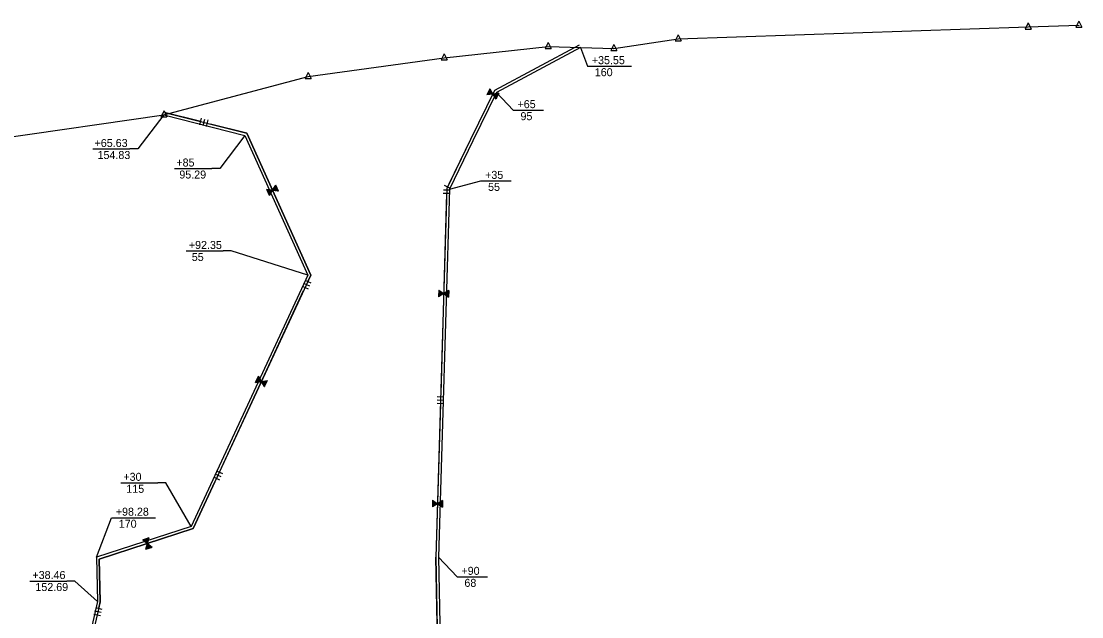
# Model space of a CAD drawing. Extents: x 979729 to 993523, y 1834148 to 1845433.
# Drawn here: x 982395 to 983190, y 1842205 to 1842651 of the extents above; entities that cross this region are included whole.
import ezdxf

# ---------------------------------------------------------------- set-up
doc = ezdxf.new("R2010")
doc.units = 0
for name, color, linetype in [('42', 7, 'Continuous'), ('51', 7, 'Continuous'), ('R_Draft', 7, 'Continuous'), ('S_EXIST_ROW', 7, 'Continuous')]:
    doc.layers.add(name, color=color, linetype=linetype)

msp = doc.modelspace()

# ---------------------------------------------------------------- linework, layer by layer
at = {"layer": '42'}
for p, q in [((982813.71, 1842632.81), (982750.2, 1842598.89)), ((982750.2, 1842598.89), (982732.24, 1842562.08)), ((982747.45, 1842598.61), (982745.78, 1842598.39)), ((982747.34, 1842598.85), (982745.91, 1842598.65)), ((982747.18, 1842599.08), (982746.04, 1842598.93)), ((982747.02, 1842599.31), (982746.18, 1842599.19)), ((982746.91, 1842599.55), (982746.31, 1842599.47)), ((982746.75, 1842599.78), (982746.44, 1842599.73)), ((982746.64, 1842600.01), (982746.57, 1842600.01)), ((982746.61, 1842600.09), (982748.89, 1842596.2)), ((982748.89, 1842596.2), (982744.42, 1842595.6)), ((982748.82, 1842596.27), (982744.46, 1842595.69)), ((982748.63, 1842596.5), (982744.59, 1842595.95)), ((982748.55, 1842596.74), (982744.73, 1842596.23)), ((982748.39, 1842596.97), (982744.86, 1842596.5)), ((982748.27, 1842597.21), (982744.99, 1842596.76)), ((982748.09, 1842597.43), (982745.12, 1842597.03)), ((982748, 1842597.68), (982745.25, 1842597.3)), ((982747.82, 1842597.9), (982745.38, 1842597.57)), ((982747.7, 1842598.14), (982745.52, 1842597.84)), ((982747.51, 1842598.37), (982745.81, 1842598.14)), ((982753.35, 1842596.8), (982748.89, 1842596.2)), ((982748.89, 1842596.2), (982751.16, 1842592.31)), ((982748.99, 1842596.19), (982751.2, 1842592.4)), ((982749.28, 1842596.19), (982751.33, 1842592.67)), ((982749.52, 1842596.26), (982751.47, 1842592.94)), ((982749.8, 1842596.28), (982751.6, 1842593.21)), ((982750.06, 1842596.34), (982751.73, 1842593.48)), ((982750.35, 1842596.33), (982751.86, 1842593.75)), ((982750.6, 1842596.41), (982751.99, 1842594.02)), ((982750.89, 1842596.4), (982752.12, 1842594.29)), ((982751.15, 1842596.46), (982752.26, 1842594.56)), ((982751.44, 1842596.45), (982752.31, 1842594.97)), ((982751.67, 1842596.55), (982752.52, 1842595.1)), ((982751.93, 1842596.61), (982752.65, 1842595.37)), ((982752.2, 1842596.63), (982752.78, 1842595.64)), ((982752.48, 1842596.65), (982752.92, 1842595.91)), ((982752.74, 1842596.7), (982753.05, 1842596.18)), ((982753.02, 1842596.72), (982753.18, 1842596.45)), ((982753.28, 1842596.77), (982753.31, 1842596.72)), ((982502.95, 1842582.46), (982564.55, 1842566.77)), ((982529.41, 1842573.14), (982530.65, 1842577.99)), ((982531.84, 1842572.53), (982533.07, 1842577.37)), ((982534.26, 1842571.91), (982535.49, 1842576.75)), ((982564.55, 1842566.77), (982612.53, 1842460.57)), ((982732.24, 1842562.08), (982714.37, 1842525.46)), ((982583.85, 1842524.05), (982586.24, 1842527.88)), ((982583.95, 1842524.06), (982586.28, 1842527.79)), ((982584.24, 1842524.05), (982586.4, 1842527.51)), ((982584.48, 1842523.97), (982586.53, 1842527.24)), ((982717.15, 1842525.45), (982712.65, 1842527.64)), ((982583.85, 1842524.05), (982579.4, 1842524.79)), ((982583.78, 1842523.98), (982579.44, 1842524.7)), ((982583.59, 1842523.76), (982579.57, 1842524.42)), ((982583.49, 1842523.52), (982579.69, 1842524.15)), ((982583.33, 1842523.3), (982579.81, 1842523.88)), ((982583.21, 1842523.06), (982579.94, 1842523.6)), ((982583.02, 1842522.84), (982580.06, 1842523.33)), ((982582.92, 1842522.6), (982580.19, 1842523.06)), ((982582.73, 1842522.38), (982580.31, 1842522.78)), ((982582.61, 1842522.15), (982580.43, 1842522.51)), ((982582.35, 1842521.69), (982580.68, 1842521.96)), ((982582.41, 1842521.93), (982580.72, 1842522.21)), ((982582.22, 1842521.45), (982580.8, 1842521.69)), ((982582.06, 1842521.23), (982580.93, 1842521.41)), ((982581.9, 1842521), (982581.05, 1842521.14)), ((982581.77, 1842520.77), (982581.17, 1842520.87)), ((982581.61, 1842520.54), (982581.3, 1842520.59)), ((982581.49, 1842520.31), (982581.42, 1842520.32)), ((982581.46, 1842520.23), (982583.85, 1842524.05)), ((982588.3, 1842523.32), (982583.85, 1842524.05)), ((982584.76, 1842523.94), (982586.65, 1842526.96)), ((982585.02, 1842523.88), (982586.77, 1842526.69)), ((982585.31, 1842523.88), (982586.9, 1842526.42)), ((982585.55, 1842523.79), (982587.02, 1842526.14)), ((982585.84, 1842523.79), (982587.14, 1842525.87)), ((982586.1, 1842523.73), (982587.27, 1842525.6)), ((982586.4, 1842523.73), (982587.3, 1842525.18)), ((982586.62, 1842523.62), (982587.52, 1842525.05)), ((982586.88, 1842523.55), (982587.64, 1842524.77)), ((982587.15, 1842523.53), (982587.76, 1842524.5)), ((982587.43, 1842523.5), (982587.89, 1842524.23)), ((982587.69, 1842523.44), (982588.01, 1842523.95)), ((982587.97, 1842523.41), (982588.13, 1842523.68)), ((982588.22, 1842523.35), (982588.26, 1842523.4)), ((982714.37, 1842525.46), (982706.26, 1842249.15)), ((982716.76, 1842521.6), (982711.76, 1842521.74)), ((982716.83, 1842524.1), (982711.83, 1842524.24)), ((982612.53, 1842460.57), (982524.29, 1842270.61)), ((982608.01, 1842456.78), (982612.55, 1842454.67)), ((982605.9, 1842452.25), (982610.44, 1842450.14)), ((982606.96, 1842454.51), (982611.49, 1842452.41)), ((982710.64, 1842447.69), (982708.29, 1842446.22)), ((982710.38, 1842447.82), (982708.3, 1842446.52)), ((982710.18, 1842447.98), (982708.31, 1842446.82)), ((982709.55, 1842448.48), (982708.33, 1842447.72)), ((982709.76, 1842448.31), (982708.33, 1842447.42)), ((982709.32, 1842448.63), (982708.34, 1842448.02)), ((982709.08, 1842448.77), (982708.35, 1842448.32)), ((982708.88, 1842448.94), (982708.36, 1842448.62)), ((982708.64, 1842449.09), (982708.37, 1842448.92)), ((982708.38, 1842449.31), (982712.06, 1842446.7)), ((982708.44, 1842449.25), (982708.38, 1842449.22)), ((982709.91, 1842448.11), (982708.46, 1842447.21)), ((982715.88, 1842449.09), (982712.06, 1842446.7)), ((982713.53, 1842447.6), (982715.79, 1842446)), ((982713.8, 1842447.72), (982715.8, 1842446.3)), ((982714.01, 1842447.87), (982715.81, 1842446.6)), ((982714.29, 1842447.98), (982715.68, 1842446.99)), ((982714.45, 1842448.17), (982715.82, 1842447.2)), ((982714.66, 1842448.33), (982715.83, 1842447.5)), ((982714.9, 1842448.46), (982715.84, 1842447.8)), ((982715.15, 1842448.59), (982715.85, 1842448.1)), ((982715.36, 1842448.75), (982715.86, 1842448.4)), ((982715.61, 1842448.88), (982715.87, 1842448.7)), ((982715.82, 1842449.04), (982715.88, 1842449)), ((982712.06, 1842446.7), (982708.23, 1842444.31)), ((982711.97, 1842446.74), (982708.24, 1842444.41)), ((982711.7, 1842446.88), (982708.25, 1842444.71)), ((982711.29, 1842447.2), (982708.26, 1842445.32)), ((982711.52, 1842447.06), (982708.26, 1842445.02)), ((982711.08, 1842447.37), (982708.27, 1842445.61)), ((982710.82, 1842447.5), (982708.28, 1842445.91)), ((982712.06, 1842446.7), (982715.73, 1842444.09)), ((982712.15, 1842446.74), (982715.73, 1842444.19)), ((982712.42, 1842446.85), (982715.74, 1842444.49)), ((982712.61, 1842447.03), (982715.75, 1842444.79)), ((982712.86, 1842447.16), (982715.76, 1842445.09)), ((982713.07, 1842447.31), (982715.77, 1842445.39)), ((982713.34, 1842447.43), (982715.78, 1842445.69)), ((982574.89, 1842380.83), (982572.88, 1842384.12)), ((982575.13, 1842380.91), (982573.01, 1842384.39)), ((982575.42, 1842380.91), (982573.13, 1842384.66)), ((982575.52, 1842380.9), (982573.18, 1842384.75)), ((982571.07, 1842380.22), (982575.52, 1842380.9)), ((982571.14, 1842380.25), (982571.11, 1842380.3)), ((982571.4, 1842380.31), (982571.24, 1842380.57)), ((982571.68, 1842380.33), (982571.36, 1842380.85)), ((982571.94, 1842380.39), (982571.49, 1842381.12)), ((982572.21, 1842380.41), (982571.62, 1842381.39)), ((982572.49, 1842380.44), (982571.74, 1842381.66)), ((982572.75, 1842380.49), (982571.87, 1842381.94)), ((982572.97, 1842380.61), (982572.08, 1842382.07)), ((982573.27, 1842380.6), (982572.12, 1842382.48)), ((982573.53, 1842380.66), (982572.25, 1842382.75)), ((982573.82, 1842380.66), (982572.38, 1842383.03)), ((982574.06, 1842380.74), (982572.5, 1842383.3)), ((982574.35, 1842380.74), (982572.63, 1842383.57)), ((982574.61, 1842380.8), (982572.75, 1842383.84)), ((982575.52, 1842380.9), (982579.98, 1842381.59)), ((982577.87, 1842377.06), (982575.52, 1842380.9)), ((982575.59, 1842380.83), (982579.94, 1842381.5)), ((982575.78, 1842380.61), (982579.81, 1842381.23)), ((982575.87, 1842380.37), (982579.68, 1842380.96)), ((982576.04, 1842380.14), (982579.56, 1842380.68)), ((982576.16, 1842379.91), (982579.43, 1842380.41)), ((982576.34, 1842379.68), (982579.3, 1842380.14)), ((982576.44, 1842379.44), (982579.18, 1842379.87)), ((982576.63, 1842379.22), (982579.05, 1842379.6)), ((982576.75, 1842378.99), (982578.92, 1842379.32)), ((982576.94, 1842378.76), (982578.63, 1842379.02)), ((982577, 1842378.52), (982578.67, 1842378.78)), ((982577.12, 1842378.29), (982578.54, 1842378.51)), ((982577.28, 1842378.06), (982578.42, 1842378.23)), ((982577.44, 1842377.83), (982578.29, 1842377.96)), ((982577.56, 1842377.59), (982578.16, 1842377.69)), ((982577.73, 1842377.37), (982578.04, 1842377.41)), ((982577.85, 1842377.13), (982577.91, 1842377.14)), ((982712.28, 1842369.16), (982707.28, 1842369.31)), ((982712.13, 1842364.17), (982707.14, 1842364.31)), ((982712.21, 1842366.66), (982707.21, 1842366.81)), ((982541.66, 1842313.94), (982546.2, 1842311.83)), ((982539.56, 1842309.4), (982544.09, 1842307.3)), ((982540.61, 1842311.67), (982545.14, 1842309.56)), ((982707.34, 1842289.31), (982703.61, 1842286.98)), ((982707.43, 1842289.27), (982703.61, 1842286.88)), ((982707.08, 1842289.44), (982703.62, 1842287.28)), ((982706.9, 1842289.63), (982703.63, 1842287.58)), ((982706.66, 1842289.77), (982703.64, 1842287.88)), ((982706.46, 1842289.94), (982703.65, 1842288.18)), ((982706.2, 1842290.07), (982703.66, 1842288.48)), ((982706.02, 1842290.25), (982703.67, 1842288.78)), ((982705.76, 1842290.38), (982703.68, 1842289.08)), ((982705.55, 1842290.55), (982703.69, 1842289.38)), ((982705.14, 1842290.88), (982703.7, 1842289.98)), ((982704.93, 1842291.05), (982703.71, 1842290.28)), ((982704.69, 1842291.19), (982703.72, 1842290.59)), ((982704.46, 1842291.34), (982703.73, 1842290.89)), ((982704.25, 1842291.51), (982703.74, 1842291.19)), ((982704.01, 1842291.65), (982703.75, 1842291.49)), ((982703.76, 1842291.88), (982707.43, 1842289.27)), ((982703.81, 1842291.82), (982703.76, 1842291.79)), ((982705.28, 1842290.68), (982703.84, 1842289.77)), ((982711.26, 1842291.66), (982707.43, 1842289.27)), ((982707.43, 1842289.27), (982711.11, 1842286.66)), ((982707.53, 1842289.31), (982711.11, 1842286.76)), ((982707.8, 1842289.42), (982711.12, 1842287.06)), ((982707.99, 1842289.59), (982711.13, 1842287.36)), ((982708.23, 1842289.73), (982711.14, 1842287.66)), ((982708.44, 1842289.88), (982711.15, 1842287.96)), ((982708.71, 1842290), (982711.16, 1842288.26)), ((982708.9, 1842290.17), (982711.16, 1842288.56)), ((982709.17, 1842290.28), (982711.17, 1842288.86)), ((982709.39, 1842290.44), (982711.18, 1842289.16)), ((982709.66, 1842290.55), (982711.06, 1842289.56)), ((982709.82, 1842290.74), (982711.2, 1842289.76)), ((982710.04, 1842290.9), (982711.21, 1842290.06)), ((982710.28, 1842291.03), (982711.22, 1842290.37)), ((982710.53, 1842291.16), (982711.23, 1842290.67)), ((982710.74, 1842291.32), (982711.23, 1842290.97)), ((982710.99, 1842291.45), (982711.24, 1842291.27)), ((982711.2, 1842291.6), (982711.25, 1842291.57)), ((982524.29, 1842270.61), (982453.98, 1842247.81)), ((982486.62, 1842262.33), (982490.16, 1842259.54)), ((982486.69, 1842262.3), (982486.71, 1842262.36)), ((982486.91, 1842262.15), (982487, 1842262.46)), ((982487.12, 1842261.96), (982487.28, 1842262.55)), ((982487.34, 1842261.82), (982487.57, 1842262.64)), ((982487.54, 1842261.63), (982487.86, 1842262.73)), ((982487.75, 1842261.44), (982488.14, 1842262.83)), ((982487.97, 1842261.29), (982488.43, 1842262.92)), ((982488.2, 1842261.21), (982488.67, 1842262.85)), ((982488.4, 1842260.98), (982489, 1842263.1)), ((982488.62, 1842260.84), (982489.29, 1842263.2)), ((982488.82, 1842260.62), (982489.57, 1842263.29)), ((982488.94, 1842255.2), (982490.16, 1842259.54)), ((982489.05, 1842260.5), (982489.86, 1842263.38)), ((982489.24, 1842260.29), (982490.14, 1842263.47)), ((982489.42, 1842256.83), (982490.74, 1842255.78)), ((982489.46, 1842260.14), (982490.43, 1842263.57)), ((982489.56, 1842257.04), (982490.9, 1842255.98)), ((982489.58, 1842257.34), (982491.31, 1842255.97)), ((982489.67, 1842259.95), (982490.71, 1842263.66)), ((982489.67, 1842257.58), (982491.6, 1842256.06)), ((982489.71, 1842257.88), (982491.88, 1842256.16)), ((982489.82, 1842258.11), (982492.17, 1842256.25)), ((982489.86, 1842258.4), (982492.46, 1842256.34)), ((982489.89, 1842259.83), (982491, 1842263.75)), ((982489.95, 1842258.64), (982492.74, 1842256.43)), ((982490, 1842258.92), (982493.03, 1842256.53)), ((982490.09, 1842259.61), (982491.28, 1842263.85)), ((982490.11, 1842259.15), (982493.31, 1842256.62)), ((982490.15, 1842259.44), (982493.6, 1842256.71)), ((982490.16, 1842259.54), (982491.38, 1842263.88)), ((982490.16, 1842259.54), (982493.69, 1842256.74)), ((982488.97, 1842255.27), (982489.03, 1842255.23)), ((982489.06, 1842255.52), (982489.31, 1842255.32)), ((982489.12, 1842255.79), (982489.6, 1842255.41)), ((982489.21, 1842256.04), (982489.88, 1842255.51)), ((982489.27, 1842256.31), (982490.17, 1842255.6)), ((982489.33, 1842256.58), (982490.46, 1842255.69)), ((982710.03, 1842041.79), (982706.26, 1842249.17)), ((982453.98, 1842247.81), (982454.62, 1842215.89)), ((982454.62, 1842215.89), (982418.19, 1842057.48)), ((982450.49, 1842209.1), (982455.37, 1842207.98)), ((982451.05, 1842211.54), (982455.93, 1842210.42)), ((982449.93, 1842206.66), (982454.8, 1842205.54))]:
    msp.add_line(p, q, dxfattribs=at)
for points in [[(982813.71, 1842632.81), (982750.2, 1842598.89), (982732.24, 1842562.08), (982716, 1842528.79)], [(982746.61, 1842600.09), (982744.42, 1842595.6)], [(982753.35, 1842596.8), (982751.16, 1842592.31)], [(982530.03, 1842575.57), (982502.95, 1842582.46)], [(982610.28, 1842455.73), (982612.53, 1842460.57), (982564.55, 1842566.77), (982537.3, 1842573.72)], [(982588.3, 1842523.32), (982586.24, 1842527.88)], [(982581.46, 1842520.23), (982579.4, 1842524.79)], [(982714.26, 1842521.67), (982709.86, 1842371.74)], [(982543.93, 1842312.88), (982607.12, 1842448.93)], [(982708.38, 1842449.31), (982708.23, 1842444.31)], [(982715.88, 1842449.09), (982715.73, 1842444.09)], [(982571.07, 1842380.22), (982573.18, 1842384.75)], [(982577.87, 1842377.06), (982579.98, 1842381.59)], [(982709.63, 1842364.24), (982706.26, 1842249.17)], [(982453.49, 1842210.98), (982454.62, 1842215.89), (982453.98, 1842247.81), (982524.29, 1842270.61), (982540.77, 1842306.08)], [(982703.76, 1842291.88), (982703.61, 1842286.88)], [(982711.26, 1842291.66), (982711.11, 1842286.66)], [(982486.62, 1842262.33), (982491.38, 1842263.88)], [(982488.94, 1842255.2), (982493.69, 1842256.74)]]:
    msp.add_lwpolyline(points, dxfattribs=at)
at = {"layer": '51'}
for p, q in [((982814.65, 1842631.05), (982751.71, 1842597.43)), ((982751.71, 1842597.43), (982734.03, 1842561.2)), ((982734.03, 1842561.2), (982716.36, 1842524.97)), ((982716.36, 1842524.97), (982708.26, 1842249.15)), ((982716.36, 1842524.97), (982716.36, 1842524.97)), ((982716.36, 1842524.97), (982716.36, 1842524.97)), ((982708.26, 1842249.15), (982712.04, 1842041.41))]:
    msp.add_line(p, q, dxfattribs=at)
for points in [[(982502.45, 1842580.53), (982563.13, 1842565.07), (982610.33, 1842460.58)], [(982610.33, 1842460.58), (982522.85, 1842272.24), (982451.95, 1842249.25), (982452.61, 1842216.09), (982413.33, 1842045.26), (982307.06, 1841994.43), (982168.6, 1842021.15)], [(982706.26, 1842249.17), (982708.18, 1842143.5)]]:
    msp.add_lwpolyline(points, dxfattribs=at)
at = {"layer": 'R_Draft'}
for p, q in [((982825.9, 1842617.05), (982852.74, 1842617.05)), ((982770.23, 1842584.11), (982786.9, 1842584.11)), ((982449.09, 1842555.01), (982476.91, 1842555.01)), ((982510.4, 1842540.38), (982538.22, 1842540.38)), ((982745.94, 1842531.12), (982762.61, 1842531.12)), ((982519.04, 1842478.62), (982546.87, 1842478.62)), ((982469.99, 1842304.95), (982497.81, 1842304.95)), ((982469.15, 1842278.8), (982495.96, 1842278.8)), ((982728.19, 1842234.52), (982744.83, 1842234.52)), ((982401.82, 1842231.4), (982429.65, 1842231.4))]:
    msp.add_line(p, q, dxfattribs=at)
for points in [[(982814.65, 1842631.05), (982819.9, 1842617.05), (982825.9, 1842617.05)], [(982751.71, 1842597.43), (982764.23, 1842584.11), (982770.23, 1842584.11)], [(982502.45, 1842580.53), (982482.91, 1842555.01), (982476.91, 1842555.01)], [(982563.13, 1842565.07), (982544.22, 1842540.38), (982538.22, 1842540.38)], [(982716.36, 1842524.97), (982739.94, 1842531.12), (982745.94, 1842531.12)], [(982610.33, 1842460.58), (982552.87, 1842478.62), (982546.87, 1842478.62)], [(982522.85, 1842272.24), (982503.81, 1842304.95), (982497.81, 1842304.95)], [(982451.95, 1842249.25), (982463.15, 1842278.8), (982469.15, 1842278.8)], [(982708.26, 1842249.15), (982722.19, 1842234.52), (982728.19, 1842234.52)], [(982452.61, 1842216.09), (982435.65, 1842231.4), (982429.65, 1842231.4)]]:
    msp.add_lwpolyline(points, dxfattribs=at)
at = {"layer": 'S_EXIST_ROW'}
for p, q in [((982887.85, 1842637.46), (983150.13, 1842646.41)), ((983150.14, 1842649.43), (983147.88, 1842644.89)), ((983150.13, 1842646.41), (983188.07, 1842647.7)), ((983150.13, 1842646.41), (983150.13, 1842646.41)), ((983150.14, 1842649.43), (983152.37, 1842644.89)), ((983188.07, 1842650.73), (983185.82, 1842646.19)), ((983188.07, 1842650.73), (983190.31, 1842646.19)), ((983188.07, 1842647.7), (983188.07, 1842647.7)), ((982887.86, 1842640.49), (982885.6, 1842635.95)), ((982887.86, 1842640.49), (982890.09, 1842635.95)), ((983147.88, 1842644.89), (983152.37, 1842644.89)), ((983185.82, 1842646.19), (983190.31, 1842646.19)), ((982712.45, 1842623.31), (982790.31, 1842631.83)), ((982790.32, 1842634.86), (982788.06, 1842630.32)), ((982790.31, 1842631.83), (982790.31, 1842631.83)), ((982790.31, 1842631.83), (982839.52, 1842630.25)), ((982790.32, 1842634.86), (982792.55, 1842630.32)), ((982839.53, 1842633.27), (982837.27, 1842628.74)), ((982839.52, 1842630.25), (982887.85, 1842637.46)), ((982839.53, 1842633.27), (982841.76, 1842628.74)), ((982885.6, 1842635.95), (982890.09, 1842635.95)), ((982887.85, 1842637.46), (982887.85, 1842637.46)), ((982610.41, 1842609.21), (982712.45, 1842623.31)), ((982712.45, 1842626.33), (982710.2, 1842621.8)), ((982712.45, 1842626.33), (982714.69, 1842621.8)), ((982712.45, 1842623.31), (982712.45, 1842623.31)), ((982788.06, 1842630.32), (982792.55, 1842630.32)), ((982837.27, 1842628.74), (982841.76, 1842628.74)), ((982839.52, 1842630.25), (982839.52, 1842630.25)), ((982710.2, 1842621.8), (982714.69, 1842621.8)), ((982502.45, 1842580.53), (982610.41, 1842609.21)), ((982610.42, 1842612.23), (982608.16, 1842607.7)), ((982608.16, 1842607.7), (982612.65, 1842607.7)), ((982610.41, 1842609.21), (982610.41, 1842609.21)), ((982610.42, 1842612.23), (982612.65, 1842607.7)), ((982502.46, 1842583.55), (982500.2, 1842579.01)), ((982502.46, 1842583.55), (982504.69, 1842579.01)), ((982377.14, 1842562.53), (982502.45, 1842580.53)), ((982500.2, 1842579.01), (982504.69, 1842579.01)), ((982502.45, 1842580.53), (982502.45, 1842580.53))]:
    msp.add_line(p, q, dxfattribs=at)
for centre, radius in [((983150.13, 1842646.41), 0.0768), ((983150.13, 1842646.41), 0.0384), ((983188.07, 1842647.7), 0.0768), ((983188.07, 1842647.7), 0.0384), ((982790.31, 1842631.83), 0.0768), ((982790.31, 1842631.83), 0.0384), ((982887.85, 1842637.46), 0.0768), ((982887.85, 1842637.46), 0.0384), ((982712.45, 1842623.31), 0.0768), ((982712.45, 1842623.31), 0.0384), ((982839.52, 1842630.25), 0.0768), ((982839.52, 1842630.25), 0.0384), ((982610.41, 1842609.21), 0.0768), ((982610.41, 1842609.21), 0.0384), ((982502.45, 1842580.53), 0.0768), ((982502.45, 1842580.53), 0.0384)]:
    msp.add_circle(centre, radius, dxfattribs=at)

# ---------------------------------------------------------------- texts
at = {"layer": 'R_Draft'}
for s, p in [('+35.55', (982823.08, 1842618.55)), (' 160', (982823.08, 1842609.55)), ('+65', (982767.4, 1842585.61)), (' 95', (982767.4, 1842576.61)), ('+65.63', (982450.41, 1842556.51)), (' 154.83', (982450.41, 1842547.51)), ('+85', (982511.72, 1842541.88)), (' 95.29', (982511.72, 1842532.88)), ('+35', (982743.11, 1842532.62)), (' 55', (982743.11, 1842523.62)), ('+92.35', (982521.06, 1842480.12)), (' 55', (982521.06, 1842471.12)), ('+30', (982472, 1842306.45)), (' 115', (982472, 1842297.45)), ('+98.28', (982466.32, 1842280.3)), (' 170', (982466.32, 1842271.3)), ('+90', (982725.37, 1842236.02)), ('+38.46', (982403.84, 1842232.9)), (' 68', (982725.37, 1842227.02)), (' 152.69', (982403.84, 1842223.9))]:
    msp.add_text(s, height=6, rotation=360, dxfattribs=at).set_placement(p)

doc.saveas('drawing.dxf')
